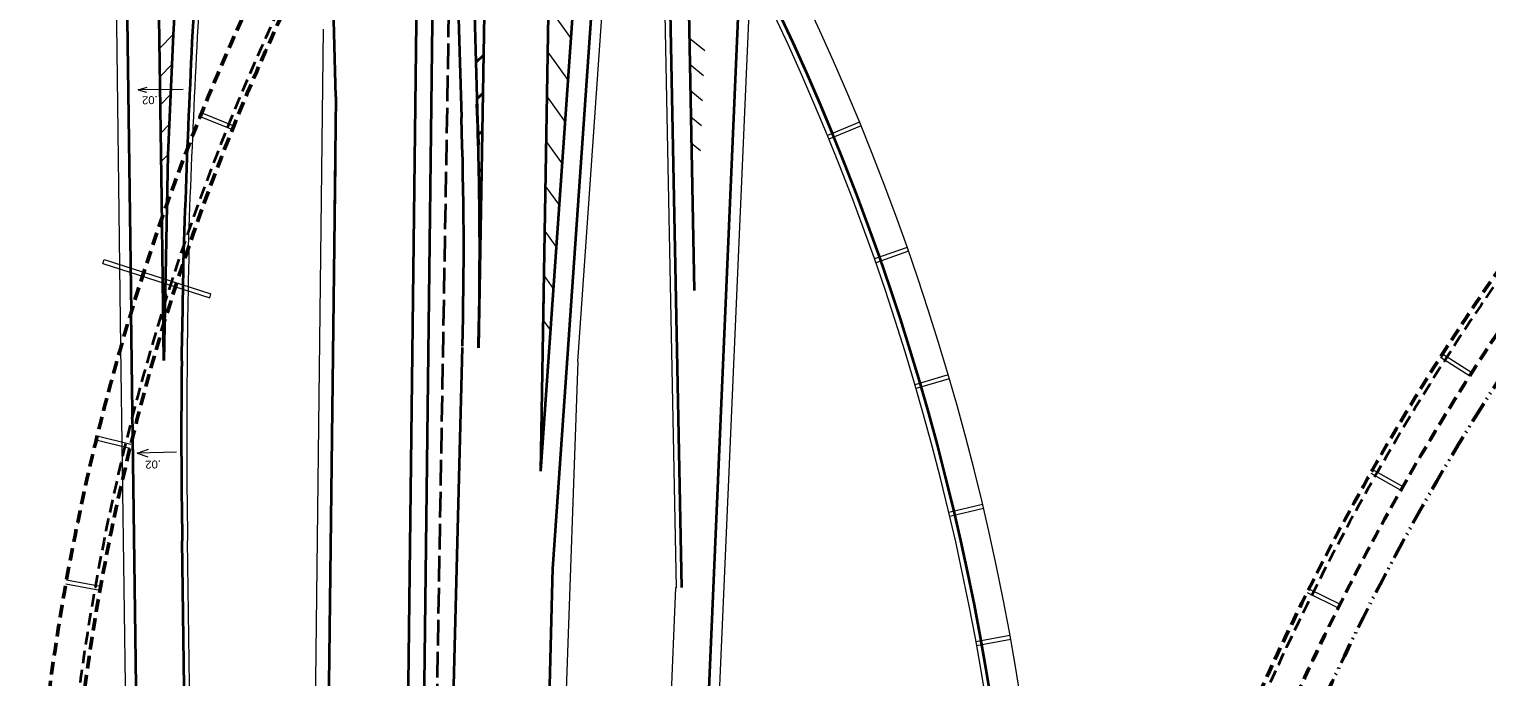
# Model space of a CAD drawing. Extents: x 2354993 to 2372084, y 6966390 to 6990057.
# Drawn here: x 2364181 to 2365274, y 6976742 to 6977227 of the extents above; entities that cross this region are included whole.
import ezdxf

# ---------------------------------------------------------------- set-up
doc = ezdxf.new("R2010")
doc.units = 0
doc.header["$LTSCALE"] = 3.2
for name, pattern in [('DASH_DOUBLE_DOT', [9.2, 5, -1.2, 0.3, -1.2, 0.3, -1.2]), ('LONG_DASHED', [7.5, 6, -1.5]), ('MEDIUM_DASHED', [4.5, 3, -1.5])]:
    doc.linetypes.add(name, pattern=pattern)
for name, color, linetype, lineweight in [('1', 7, 'Continuous', 13), ('12', 7, 'Continuous', 13), ('19', 7, 'Continuous', 13), ('2', 7, 'Continuous', 35), ('4', 7, 'Continuous', 13), ('5', 7, 'Continuous', 35), ('60', 7, 'DASH_DOUBLE_DOT', 53)]:
    doc.layers.add(name, color=color, linetype=linetype, lineweight=lineweight)

msp = doc.modelspace()

# ---------------------------------------------------------------- linework, layer by layer
at = {"layer": '1', "lineweight": 35}
msp.add_line((2364566.988, 6977018.372), (2364567.153, 6977024.857), dxfattribs=at)
msp.add_arc((2361642.876, 6977062.444), 2864.29, 358.54589, 1.97449, dxfattribs=at)
at = {"layer": '12'}
for p, q in [((2364309.664, 6977162.056), (2364333.781, 6977152.341)), ((2364310.787, 6977164.838), (2364334.905, 6977155.122)), ((2364803.818, 6977157.669), (2364779.77, 6977147.786)), ((2364804.955, 6977154.894), (2364780.908, 6977145.011)), ((2364839.541, 6977063.832), (2364815.008, 6977055.221)), ((2364236.752, 6977051.898), (2364237.672, 6977054.755)), ((2364237.672, 6977054.755), (2364317.676, 6977029.033)), ((2364840.532, 6977061), (2364816, 6977052.389)), ((2364236.752, 6977051.898), (2364316.757, 6977026.176)), ((2364316.757, 6977026.176), (2364317.676, 6977029.033)), ((2365239.209, 6976981.492), (2365261.181, 6976967.59)), ((2365240.825, 6976984.019), (2365262.797, 6976970.118)), ((2364870.304, 6976968.253), (2364845.355, 6976960.937)), ((2364871.145, 6976965.374), (2364846.196, 6976958.058)), ((2364232.453, 6976922.528), (2364257.703, 6976916.329)), ((2364231.738, 6976919.615), (2364256.99, 6976913.416)), ((2365186.982, 6976894.691), (2365209.651, 6976881.958)), ((2365188.462, 6976897.3), (2365211.131, 6976884.566)), ((2364896.023, 6976871.195), (2364870.725, 6976865.196)), ((2364896.712, 6976868.276), (2364871.414, 6976862.277)), ((2364235.035, 6976809.704), (2364209.446, 6976814.314)), ((2364234.505, 6976806.752), (2364208.917, 6976811.362)), ((2365139.375, 6976805.243), (2365162.678, 6976793.713)), ((2365140.716, 6976807.927), (2365164.02, 6976796.396)), ((2364916.626, 6976772.925), (2364891.049, 6976768.257)), ((2364917.162, 6976769.973), (2364891.584, 6976765.306))]:
    msp.add_line(p, q, dxfattribs=at)
at = {"layer": '19'}
for p, q in [((2364263.06, 6977181.975), (2364269.482, 6977180.223)), ((2364262.384, 6976909.676), (2364270.522, 6976906.947))]:
    msp.add_line(p, q, dxfattribs=at)
for points in [[(2364296.953, 6977182.299), (2364263.06, 6977181.975), (2364269.983, 6977184.084)], [(2364291.988, 6976910.466), (2364262.384, 6976909.676), (2364270.848, 6976912.562)]]:
    msp.add_lwpolyline(points, dxfattribs=at)
at = {"layer": '2'}
msp.add_line((2364295.791, 6976978.965), (2364296.078, 6977000.711), dxfattribs=at)
for centre, radius, start, end in [((2372851.201, 6976799.233), 8557.951, 176.61424, 178.30543), ((2370011.158, 6976925.227), 5715.578, 178.726, 179.24328), ((2369221.259, 6976924.671), 4925.767, 179.36845, 180.93883)]:
    msp.add_arc(centre, radius, start, end, dxfattribs=at)
at = {"layer": '4'}
msp.add_line((2364592.679, 6976978.427), (2364625.192, 6977445.625), dxfattribs=at)
at = {"layer": '5', "lineweight": 13}
for p, q in [((2364250.238, 6976989.323), (2364238.582, 6977875.031)), ((2364655.625, 6977359.311), (2364666.287, 6976808.765)), ((2364690.072, 6976527.283), (2364724.81, 6977326.163)), ((2364570.688, 6977243.894), (2364587.585, 6977220.334)), ((2364401.898, 6977227.474), (2364393.18, 6976501.87)), ((2364279.294, 6977213.117), (2364289.347, 6977223.458)), ((2364676.309, 6977220.826), (2364687.791, 6977211.405)), ((2364570.147, 6977210.331), (2364585.412, 6977189.044)), ((2364279.574, 6977191.884), (2364288.208, 6977200.768)), ((2364676.691, 6977201.109), (2364686.976, 6977192.671)), ((2364279.853, 6977170.657), (2364287.166, 6977178.179)), ((2364569.605, 6977176.767), (2364583.24, 6977157.755)), ((2364677.073, 6977181.395), (2364686.162, 6977173.939)), ((2364677.455, 6977161.681), (2364685.347, 6977155.204)), ((2364280.133, 6977149.424), (2364286.216, 6977155.682)), ((2364569.064, 6977143.204), (2364581.068, 6977126.465)), ((2364677.836, 6977141.967), (2364684.532, 6977136.472)), ((2364280.412, 6977128.187), (2364285.358, 6977133.277)), ((2364568.522, 6977109.641), (2364578.896, 6977095.176)), ((2364567.981, 6977076.077), (2364576.724, 6977063.886)), ((2364567.44, 6977042.514), (2364574.551, 6977032.597)), ((2364566.898, 6977008.95), (2364572.379, 6977001.307)), ((2364256.409, 6976520.423), (2364250.238, 6976989.323)), ((2364592.679, 6976978.427), (2364576.375, 6976521.182)), ((2364304.541, 6976510.635), (2364300.153, 6976844.016)), ((2364653.122, 6976506.192), (2364666.284, 6976808.9))]:
    msp.add_line(p, q, dxfattribs=at)
at = {"layer": '5'}
for p, q in [((2364246.695, 6977868.679), (2364257.91, 6977015.279)), ((2364280.781, 6977100.108), (2364270.924, 6977849.204)), ((2364518.585, 6976988.524), (2364528.853, 6977616.591)), ((2364565.082, 6976896.195), (2364576.847, 6977615.806)), ((2364411.249, 6977176.688), (2364406.277, 6977364.018)), ((2364659.624, 6977359.388), (2364670.286, 6976808.842)), ((2364673.621, 6977359.659), (2364679.974, 6977031.633)), ((2364463.051, 6976501.012), (2364473.085, 6977351.601)), ((2364468.806, 6975971.515), (2364485.084, 6977351.459)), ((2364683.134, 6976551.86), (2364717.405, 6977340.009)), ((2364565.082, 6976896.195), (2364591.695, 6977279.547)), ((2364574.032, 6976822.971), (2364605.662, 6977278.577)), ((2364516.32, 6977202.401), (2364522.175, 6977208.121)), ((2364411.249, 6977176.697), (2364410.263, 6977088.749)), ((2364517.2, 6977175.305), (2364521.711, 6977179.711)), ((2364518.081, 6977148.209), (2364521.246, 6977151.3)), ((2364410.695, 6977127.236), (2364403.178, 6976501.747)), ((2364518.533, 6977120.695), (2364520.782, 6977122.891)), ((2364282.372, 6976979.158), (2364280.781, 6977100.108)), ((2364518.968, 6977093.163), (2364520.317, 6977094.481)), ((2364264.089, 6976544.74), (2364257.91, 6977015.279)), ((2364493.827, 6976500.634), (2364506.22, 6976988.835)), ((2364300.388, 6976522.254), (2364296.153, 6976843.963)), ((2364565.808, 6976498.964), (2364574.043, 6976823.383))]:
    msp.add_line(p, q, dxfattribs=at)
at = {"layer": '5', "linetype": 'LONG_DASHED'}
msp.add_line((2364483.383, 6976501.515), (2364499.337, 6977426.187), dxfattribs=at)
at = {"layer": '5'}
msp.add_lwpolyline([(2364297.345, 6977361.394), (2364293.339, 6977292.123), (2364289.347, 6977223.458), (2364285.358, 6977133.277), (2364282.372, 6976979.158)], dxfattribs=at)
at = {"layer": '5', "linetype": 'MEDIUM_DASHED', "lineweight": 53}
for centre, radius, start, end in [((2366864.416, 6975944.503), 1927.859, 114.19653, 168.16581), ((2366864.416, 6975944.503), 1901.859, 114.19652, 168.16581), ((2365952.337, 6976500.333), 1770.947, 142.90202, 179.54796), ((2365952.338, 6976500.332), 1744.947, 143.1512, 179.53746)]:
    msp.add_arc(centre, radius, start, end, dxfattribs=at)
at = {"layer": '5', "linetype": 'MEDIUM_DASHED'}
for centre, radius, start, end in [((2366864.416, 6975944.503), 1923.859, 114.19652, 168.16581), ((2365952.338, 6976500.332), 1748.947, 143.1115, 179.53746)]:
    msp.add_arc(centre, radius, start, end, dxfattribs=at)
at = {"layer": '5', "lineweight": 13}
for centre, radius, start, end in [((2363030.028, 6976428.641), 1917.859, 350.16881, 38.12295), ((2363030.028, 6976428.641), 1891.859, 350.16881, 38.12295), ((2373046.888, 6976763.367), 8751.449, 176.45552, 178.03092), ((2370011.159, 6976925.25), 5711.578, 178.59763, 179.24066), ((2370025.158, 6976925.064), 5725.578, 179.24066, 180.81104)]:
    msp.add_arc(centre, radius, start, end, dxfattribs=at)
at = {"layer": '5'}
for centre, radius, start, end in [((2363030.028, 6976428.641), 1895.859, 350.16881, 38.12295), ((2370231.641, 6977358.541), 5729.578, 179.32409, 181.97449), ((2370231.641, 6977358.541), 5717.578, 179.32409, 182.18622), ((2361642.852, 6977061.52), 2876.29, 358.54589, 2.18622)]:
    msp.add_arc(centre, radius, start, end, dxfattribs=at)
at = {"layer": '60'}
msp.add_arc((2366864.416, 6975944.503), 1881.859, 114.65077, 155.69784, dxfattribs=at)

# ---------------------------------------------------------------- texts
at = {"layer": '19', "width": 1.05}
for rotation, p in [(181.429, (2364277.701, 6977177.399)), (181.793, (2364280.158, 6976904.322))]:
    msp.add_text('.02', height=6, rotation=rotation, dxfattribs=at).set_placement(p)

doc.saveas('drawing.dxf')
